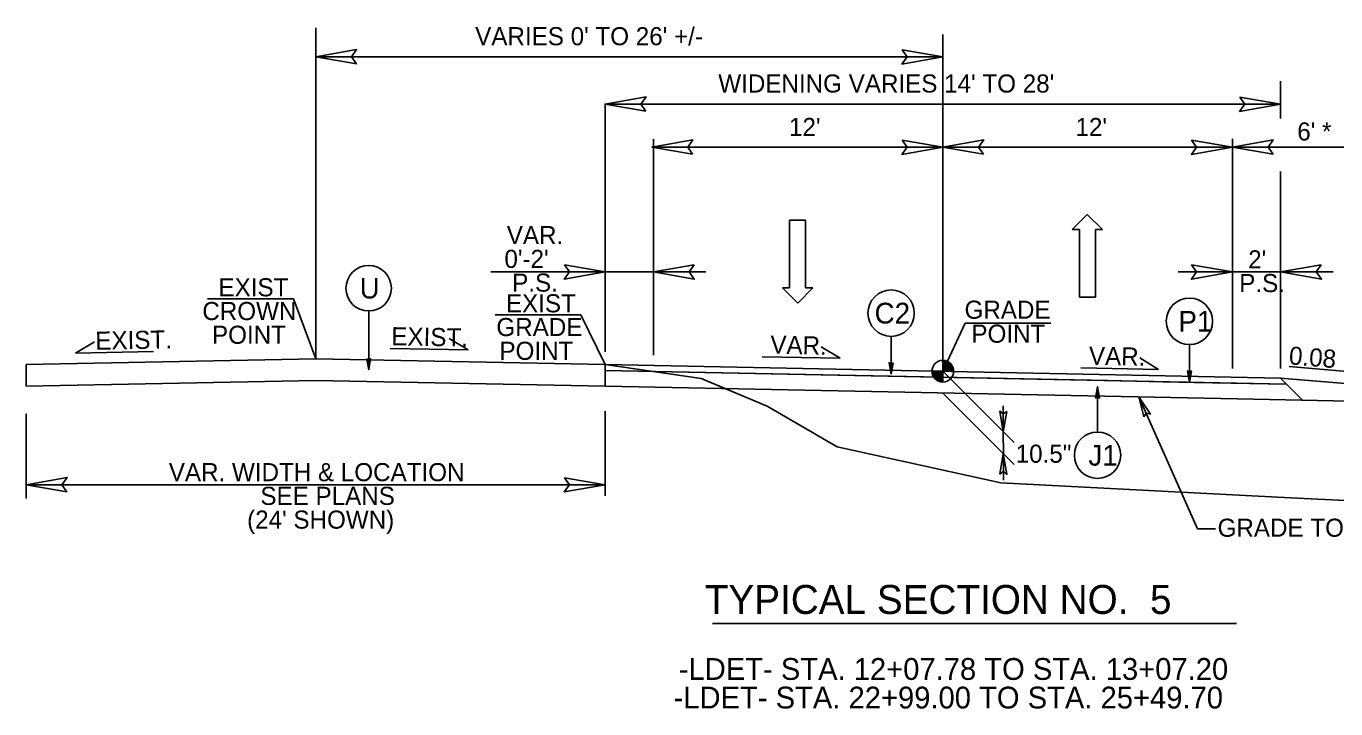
# Model space of a CAD drawing. Extents: x 1548135 to 1549339, y 868664 to 869085.
# Drawn here: x 1548331.5 to 1548385.7, y 868808.6 to 868836.9 of the extents above; entities that cross this region are included whole.
import ezdxf

# ---------------------------------------------------------------- set-up
doc = ezdxf.new("R2010")
doc.units = 0
for name, color, linetype in [('P_RDY_TC_Pvmt_Asphalt_Base_Course', 7, 'Continuous'), ('Prop Terminator CELL', 7, 'Continuous'), ('Sheet_Plan', 7, 'Continuous'), ('Typical Curb CELL', 7, 'Continuous'), ('Typical Grade Point Symbol CELL', 7, 'Continuous'), ('Typical Hinge Slope Arterial CELL', 7, 'Continuous'), ('Typical Hinge Slope Interstate CELL', 7, 'Continuous'), ('Typical Pavement Slope Information CELL', 7, 'Continuous'), ('Typical Shoulder Slope CELL', 7, 'Continuous'), ('Typical Shoulder Slope Information CELL', 7, 'Continuous'), ('Typical Terminator CELL', 7, 'Continuous'), ('Typical Text Centerline CELL', 7, 'Continuous'), ('Typical Text General CELL', 7, 'Continuous'), ('Typical Text Grade Point CELL', 7, 'Continuous'), ('Typical Text ID Circle CELL', 7, 'Continuous'), ('z - Construction', 7, 'Continuous')]:
    doc.layers.add(name, color=color, linetype=linetype)

msp = doc.modelspace()

# ---------------------------------------------------------------- linework, layer by layer
at = {"layer": 'P_RDY_TC_Pvmt_Asphalt_Base_Course'}
for points in [[(1548345.142, 868835.342), (1548343.455, 868835.633), (1548345.152, 868835.933), (1548344.936, 868835.633)], [(1548367.767, 868835.923), (1548369.455, 868835.633), (1548367.758, 868835.333), (1548367.974, 868835.633)], [(1548357.142, 868833.383), (1548355.455, 868833.674), (1548357.152, 868833.974), (1548356.936, 868833.674)], [(1548381.767, 868833.965), (1548383.455, 868833.674), (1548381.758, 868833.374), (1548381.974, 868833.674)], [(1548359.083, 868831.601), (1548357.395, 868831.891), (1548359.092, 868832.191), (1548358.877, 868831.891)], [(1548367.767, 868832.182), (1548369.455, 868831.891), (1548367.758, 868831.591), (1548367.974, 868831.891)], [(1548371.142, 868831.601), (1548369.455, 868831.891), (1548371.152, 868832.191), (1548370.936, 868831.891)], [(1548379.767, 868832.182), (1548381.455, 868831.891), (1548379.758, 868831.591), (1548379.974, 868831.891)], [(1548383.142, 868831.601), (1548381.455, 868831.891), (1548383.152, 868832.191), (1548382.936, 868831.891)], [(1548353.767, 868827.009), (1548355.455, 868826.718), (1548353.758, 868826.418), (1548353.974, 868826.718)], [(1548359.142, 868827.009), (1548357.455, 868826.718), (1548359.152, 868826.418), (1548358.936, 868826.718)], [(1548379.767, 868827.009), (1548381.455, 868826.718), (1548379.758, 868826.418), (1548379.974, 868826.718)], [(1548385.142, 868827.009), (1548383.455, 868826.718), (1548385.152, 868826.418), (1548384.936, 868826.718)], [(1548333.142, 868817.613), (1548331.455, 868817.904), (1548333.151, 868818.204), (1548332.936, 868817.904)], [(1548353.767, 868818.194), (1548355.455, 868817.904), (1548353.758, 868817.604), (1548353.974, 868817.904)]]:
    msp.add_lwpolyline(points, close=True, dxfattribs=at)
at = {"layer": 'Prop Terminator CELL'}
msp.add_lwpolyline([(1548355.455, 868822.885), (1548383.455, 868822.325), (1548383.705, 868822.07), (1548379.88, 868822.146), (1548378.58, 868822.172), (1548376.296, 868822.218), (1548355.455, 868822.635), (1548355.455, 868822.635)], close=True, dxfattribs=at)
at = {"layer": 'Sheet_Plan'}
msp.add_line((1548387.466, 868821.991), (1548383.455, 868822.325), dxfattribs=at)
at = {"layer": 'Typical Curb CELL'}
for p, q in [((1548369.455, 868822.605), (1548369.455, 868823.053)), ((1548369.007, 868822.605), (1548369.455, 868822.605)), ((1548369.454, 868822.157), (1548369.455, 868822.605)), ((1548369.455, 868822.605), (1548369.454, 868822.157)), ((1548369.902, 868822.605), (1548369.455, 868822.605))]:
    msp.add_line(p, q, dxfattribs=at)
for points in [[(1548369.459, 868823.053), (1548369.459, 868823.053), (1548369.459, 868822.605)], [(1548369.468, 868823.053), (1548369.468, 868822.605)], [(1548369.477, 868823.052), (1548369.477, 868822.605)], [(1548369.486, 868823.052), (1548369.486, 868822.605)], [(1548369.495, 868823.051), (1548369.495, 868822.605)], [(1548369.503, 868823.05), (1548369.503, 868822.605)], [(1548369.512, 868823.049), (1548369.512, 868822.605)], [(1548369.521, 868823.048), (1548369.521, 868822.605)], [(1548369.53, 868823.047), (1548369.53, 868822.605)], [(1548369.539, 868823.045), (1548369.539, 868822.605)], [(1548369.548, 868823.043), (1548369.548, 868822.605)], [(1548369.557, 868823.041), (1548369.557, 868822.605)], [(1548369.566, 868823.039), (1548369.566, 868822.605)], [(1548369.575, 868823.036), (1548369.575, 868822.605)], [(1548369.584, 868823.034), (1548369.584, 868822.605)], [(1548369.593, 868823.031), (1548369.593, 868822.605)], [(1548369.602, 868823.028), (1548369.602, 868822.605)], [(1548369.611, 868823.025), (1548369.611, 868822.605)], [(1548369.62, 868823.021), (1548369.62, 868822.605)], [(1548369.629, 868823.017), (1548369.629, 868822.605)], [(1548369.638, 868823.013), (1548369.638, 868822.605)], [(1548369.647, 868823.009), (1548369.647, 868822.605)], [(1548369.656, 868823.005), (1548369.656, 868822.605)], [(1548369.665, 868823), (1548369.665, 868822.605)], [(1548369.674, 868822.995), (1548369.674, 868822.605)], [(1548369.683, 868822.99), (1548369.683, 868822.605)], [(1548369.691, 868822.985), (1548369.691, 868822.605)], [(1548369.7, 868822.979), (1548369.7, 868822.605)], [(1548369.709, 868822.973), (1548369.709, 868822.605)], [(1548369.718, 868822.966), (1548369.718, 868822.605)], [(1548369.727, 868822.96), (1548369.727, 868822.605)], [(1548369.736, 868822.953), (1548369.736, 868822.605)], [(1548369.745, 868822.945), (1548369.745, 868822.605)], [(1548369.754, 868822.937), (1548369.754, 868822.605)], [(1548369.763, 868822.929), (1548369.763, 868822.605)], [(1548369.772, 868822.92), (1548369.772, 868822.605)], [(1548369.781, 868822.911), (1548369.781, 868822.605)], [(1548369.79, 868822.901), (1548369.79, 868822.605)], [(1548369.799, 868822.89), (1548369.799, 868822.605)], [(1548369.808, 868822.879), (1548369.808, 868822.605)], [(1548369.817, 868822.868), (1548369.817, 868822.605)], [(1548369.826, 868822.855), (1548369.826, 868822.605)], [(1548369.835, 868822.841), (1548369.835, 868822.605)], [(1548369.009, 868822.605), (1548369.009, 868822.556)], [(1548369.018, 868822.605), (1548369.018, 868822.503)], [(1548369.027, 868822.605), (1548369.027, 868822.472)], [(1548369.036, 868822.605), (1548369.036, 868822.445)], [(1548369.045, 868822.605), (1548369.045, 868822.424)], [(1548369.054, 868822.605), (1548369.054, 868822.405)], [(1548369.063, 868822.605), (1548369.063, 868822.388)], [(1548369.072, 868822.605), (1548369.072, 868822.372)], [(1548369.081, 868822.605), (1548369.081, 868822.358)], [(1548369.09, 868822.605), (1548369.09, 868822.345)], [(1548369.099, 868822.605), (1548369.099, 868822.333)], [(1548369.108, 868822.605), (1548369.108, 868822.322)], [(1548369.117, 868822.605), (1548369.117, 868822.312)], [(1548369.126, 868822.605), (1548369.126, 868822.302)], [(1548369.134, 868822.605), (1548369.134, 868822.292)], [(1548369.143, 868822.605), (1548369.143, 868822.283)], [(1548369.152, 868822.605), (1548369.152, 868822.275)], [(1548369.161, 868822.605), (1548369.161, 868822.267)], [(1548369.17, 868822.605), (1548369.17, 868822.259)], [(1548369.179, 868822.605), (1548369.179, 868822.252)], [(1548369.188, 868822.605), (1548369.188, 868822.245)], [(1548369.197, 868822.605), (1548369.197, 868822.239)], [(1548369.206, 868822.605), (1548369.206, 868822.233)], [(1548369.215, 868822.605), (1548369.215, 868822.227)], [(1548369.224, 868822.605), (1548369.224, 868822.221)], [(1548369.233, 868822.605), (1548369.233, 868822.216)], [(1548369.242, 868822.605), (1548369.242, 868822.211)], [(1548369.251, 868822.605), (1548369.251, 868822.206)], [(1548369.26, 868822.605), (1548369.26, 868822.202)], [(1548369.269, 868822.605), (1548369.269, 868822.198)], [(1548369.278, 868822.605), (1548369.278, 868822.194)], [(1548369.287, 868822.605), (1548369.287, 868822.19)], [(1548369.296, 868822.605), (1548369.296, 868822.186)], [(1548369.305, 868822.605), (1548369.305, 868822.183)], [(1548369.313, 868822.605), (1548369.313, 868822.18)], [(1548369.322, 868822.605), (1548369.322, 868822.177)], [(1548369.331, 868822.605), (1548369.331, 868822.175)], [(1548369.34, 868822.605), (1548369.34, 868822.172)], [(1548369.349, 868822.605), (1548369.349, 868822.17)], [(1548369.358, 868822.605), (1548369.358, 868822.168)], [(1548369.367, 868822.605), (1548369.367, 868822.166)], [(1548369.376, 868822.605), (1548369.376, 868822.164)], [(1548369.385, 868822.605), (1548369.385, 868822.163)], [(1548369.394, 868822.605), (1548369.394, 868822.161)], [(1548369.403, 868822.605), (1548369.403, 868822.16)], [(1548369.412, 868822.605), (1548369.412, 868822.159)], [(1548369.421, 868822.605), (1548369.421, 868822.158)], [(1548369.43, 868822.605), (1548369.43, 868822.158)], [(1548369.439, 868822.605), (1548369.439, 868822.157)], [(1548369.448, 868822.605), (1548369.448, 868822.157), (1548369.448, 868822.157)], [(1548369.844, 868822.826), (1548369.844, 868822.605)], [(1548369.853, 868822.81), (1548369.853, 868822.605)], [(1548369.862, 868822.791), (1548369.862, 868822.605)], [(1548369.87, 868822.77), (1548369.87, 868822.605)], [(1548369.879, 868822.745), (1548369.879, 868822.605)], [(1548369.888, 868822.714), (1548369.888, 868822.605)], [(1548369.897, 868822.669), (1548369.897, 868822.605)]]:
    msp.add_lwpolyline(points, dxfattribs=at)
msp.add_circle((1548369.454, 868822.605), 0.448, dxfattribs=at)
for start, end in [(359.9905, 89.9905), (179.9905, 269.9905)]:
    msp.add_arc((1548369.454, 868822.605), 0.448, start, end, dxfattribs=at)
at = {"layer": 'Typical Grade Point Symbol CELL'}
for p, q in [((1548343.455, 868823.165), (1548343.455, 868836.836)), ((1548369.455, 868822.605), (1548369.455, 868836.556)), ((1548355.455, 868835.633), (1548343.455, 868835.633)), ((1548355.455, 868835.633), (1548369.455, 868835.633)), ((1548383.455, 868833.081), (1548383.455, 868834.627)), ((1548369.455, 868833.674), (1548355.455, 868833.674)), ((1548369.455, 868833.674), (1548383.455, 868833.674)), ((1548357.455, 868823.272), (1548357.455, 868832.217)), ((1548381.455, 868822.725), (1548381.455, 868832.237)), ((1548381.455, 868822.725), (1548381.455, 868832.237)), ((1548369.455, 868831.891), (1548357.455, 868831.891)), ((1548369.455, 868831.891), (1548387.466, 868831.891)), ((1548383.455, 868822.725), (1548383.455, 868830.875)), ((1548350.711, 868826.718), (1548359.635, 868826.718)), ((1548379.205, 868826.718), (1548385.635, 868826.718))]:
    msp.add_line(p, q, dxfattribs=at)
at = {"layer": 'Typical Hinge Slope Arterial CELL'}
for p, q in [((1548342.531, 868825.611), (1548338.974, 868825.611)), ((1548354.447, 868824.947), (1548350.89, 868824.947)), ((1548370.378, 868824.591), (1548373.935, 868824.591))]:
    msp.add_line(p, q, dxfattribs=at)
at = {"layer": 'Typical Hinge Slope Interstate CELL'}
for p, q in [((1548345.652, 868825.102), (1548345.652, 868822.666)), ((1548367.31, 868824.051), (1548367.31, 868822.489)), ((1548379.675, 868823.713), (1548379.675, 868822.15)), ((1548343.455, 868823.125), (1548331.455, 868822.885)), ((1548331.455, 868821.985), (1548331.455, 868822.885)), ((1548343.455, 868823.125), (1548355.455, 868822.885)), ((1548355.455, 868822.885), (1548355.455, 868821.985)), ((1548383.705, 868822.07), (1548355.455, 868822.635)), ((1548372.406, 868819.653), (1548369.455, 868822.605)), ((1548343.455, 868822.225), (1548331.455, 868821.985)), ((1548343.455, 868822.225), (1548355.455, 868821.985)), ((1548381.675, 868821.46), (1548355.455, 868821.985)), ((1548375.867, 868820.086), (1548375.867, 868821.964)), ((1548372.405, 868818.743), (1548369.453, 868821.695)), ((1548371.96, 868821.178), (1548371.962, 868818.088))]:
    msp.add_line(p, q, dxfattribs=at)
for points in [[(1548345.573, 868823.125), (1548345.652, 868822.666), (1548345.734, 868823.128), (1548345.652, 868823.069)], [(1548367.391, 868822.957), (1548367.31, 868822.489), (1548367.227, 868822.96), (1548367.31, 868822.9)], [(1548379.756, 868822.619), (1548379.675, 868822.15), (1548379.592, 868822.622), (1548379.675, 868822.562)], [(1548375.786, 868821.496), (1548375.867, 868821.964), (1548375.95, 868821.493), (1548375.867, 868821.553)], [(1548377.789, 868820.712), (1548377.58, 868821.542), (1548378.061, 868820.828), (1548377.88, 868820.865)], [(1548372.105, 868820.944), (1548371.96, 868820.1), (1548371.81, 868820.948), (1548371.96, 868820.841)], [(1548371.814, 868818.345), (1548371.96, 868819.189), (1548372.11, 868818.34), (1548371.96, 868818.448)]]:
    msp.add_lwpolyline(points, close=True, dxfattribs=at)
for points in [[(1548355.455, 868822.885), (1548359.435, 868822.302), (1548362.167, 868821.156), (1548365.071, 868819.475), (1548371.864, 868817.984), (1548383.869, 868817.359), (1548398.104, 868816.672)], [(1548377.58, 868821.542), (1548380.004, 868816.077), (1548380.755, 868816.077)]]:
    msp.add_lwpolyline(points, dxfattribs=at)
for centre, radius in [((1548345.652, 868826.044), 0.942), ((1548367.31, 868825.013), 0.962), ((1548379.675, 868824.674), 0.962), ((1548375.867, 868819.125), 0.962)]:
    msp.add_circle(centre, radius, dxfattribs=at)
at = {"layer": 'Typical Pavement Slope Information CELL'}
for p, q in [((1548349.777, 868823.487), (1548348.994, 868823.961)), ((1548333.504, 868823.357), (1548334.287, 868823.83)), ((1548333.504, 868823.357), (1548336.733, 868823.422)), ((1548349.777, 868823.487), (1548346.547, 868823.552)), ((1548365.191, 868823.144), (1548364.408, 868823.618)), ((1548365.191, 868823.144), (1548361.962, 868823.209)), ((1548378.398, 868822.683), (1548377.615, 868823.156)), ((1548378.398, 868822.683), (1548375.168, 868822.748)), ((1548386.688, 868822.556), (1548383.805, 868822.797))]:
    msp.add_line(p, q, dxfattribs=at)
at = {"layer": 'Typical Shoulder Slope CELL'}
for p, q in [((1548342.531, 868825.611), (1548343.455, 868823.125)), ((1548354.447, 868824.947), (1548355.455, 868822.885)), ((1548370.378, 868824.591), (1548369.455, 868822.605))]:
    msp.add_line(p, q, dxfattribs=at)
at = {"layer": 'Typical Shoulder Slope Information CELL'}
for p, q in [((1548363.101, 868826.061), (1548363.101, 868828.861)), ((1548363.101, 868828.861), (1548363.761, 868828.861)), ((1548363.761, 868828.861), (1548363.761, 868826.061)), ((1548374.819, 868828.475), (1548375.439, 868829.105)), ((1548375.439, 868829.105), (1548376.079, 868828.475)), ((1548375.119, 868828.475), (1548374.819, 868828.475)), ((1548375.119, 868825.675), (1548375.119, 868828.475)), ((1548376.079, 868828.475), (1548375.779, 868828.475)), ((1548375.779, 868828.475), (1548375.779, 868825.675)), ((1548363.441, 868825.431), (1548362.801, 868826.061)), ((1548362.801, 868826.061), (1548363.101, 868826.061)), ((1548364.061, 868826.061), (1548363.441, 868825.431)), ((1548363.761, 868826.061), (1548364.061, 868826.061)), ((1548375.779, 868825.675), (1548375.119, 868825.675))]:
    msp.add_line(p, q, dxfattribs=at)
at = {"layer": 'Typical Terminator CELL'}
for p, q in [((1548331.455, 868817.333), (1548331.455, 868820.836)), ((1548355.455, 868817.449), (1548355.455, 868820.952)), ((1548331.455, 868817.904), (1548355.455, 868817.904)), ((1548359.903, 868812.148), (1548381.624, 868812.148))]:
    msp.add_line(p, q, dxfattribs=at)
at = {"layer": 'Typical Text Grade Point CELL'}
for p, q in [((1548355.455, 868822.885), (1548383.455, 868822.325)), ((1548383.455, 868822.325), (1548384.357, 868821.406)), ((1548381.675, 868821.46), (1548388.814, 868821.317))]:
    msp.add_line(p, q, dxfattribs=at)
at = {"layer": 'Typical Text ID Circle CELL'}
msp.add_line((1548355.455, 868833.674), (1548355.455, 868823.413), dxfattribs=at)

# ---------------------------------------------------------------- texts
at = {"layer": 'Typical Hinge Slope Arterial CELL'}
msp.add_text('TYPICAL SECTION NO.  5', height=1.2, dxfattribs=at).set_placement((1548359.584, 868812.55))
at = {"layer": 'Typical Hinge Slope Interstate CELL'}
for s, height, p in [('U', 0.844, (1548345.285, 868825.622)), ('C2', 0.8608, (1548366.624, 868824.582)), ('P1', 0.8608, (1548379.219, 868824.244)), ('10.5"', 0.75, (1548372.474, 868818.814)), ('J1', 0.8608, (1548375.488, 868818.694)), ('GRADE TO THIS LINE', 0.75, (1548380.843, 868815.747))]:
    msp.add_text(s, height=height, dxfattribs=at).set_placement(p)
at = {"layer": 'Typical Pavement Slope Information CELL'}
for s, rotation, p in [('EXIST.', 1.1456, (1548334.327, 868823.493)), ('EXIST.', 358.8544, (1548346.585, 868823.686)), ('VAR.', 358.8544, (1548362.297, 868823.337)), ('VAR.', 358.8544, (1548375.503, 868822.876))]:
    msp.add_text(s, height=0.75, rotation=rotation, dxfattribs=at).set_placement(p)
at = {"layer": 'Typical Shoulder Slope CELL'}
for s, p in [("VARIES 0' TO 26' +/-", (1548350.068, 868836.112)), ("WIDENING VARIES 14' TO 28'", (1548360.146, 868834.153)), ("12'", (1548363.077, 868832.352)), ("12'", (1548374.954, 868832.352)), ("6' *", (1548384.147, 868832.166)), ('EXIST', (1548339.426, 868825.709)), ('EXIST', (1548351.342, 868825.045)), ('CROWN', (1548338.757, 868824.725)), ('GRADE', (1548370.353, 868824.781)), ('POINT', (1548339.157, 868823.742)), ('GRADE', (1548350.946, 868824.062)), ('POINT', (1548370.638, 868823.787)), ('POINT', (1548351.072, 868823.078)), ('VAR. WIDTH & LOCATION', (1548337.366, 868818.05)), ('SEE PLANS', (1548341.163, 868817.067)), ("(24' SHOWN)", (1548340.613, 868816.084))]:
    msp.add_text(s, height=0.75, dxfattribs=at).set_placement(p)
at = {"layer": 'Typical Text Centerline CELL'}
for s, p in [('VAR. ', (1548351.377, 868827.871)), ("0'-2'", (1548351.28, 868826.887)), ("2'", (1548382.11, 868826.867)), ('P.S.', (1548351.601, 868825.904)), ('P.S.', (1548381.741, 868825.884))]:
    msp.add_text(s, height=0.75, dxfattribs=at).set_placement(p)
at = {"layer": 'Typical Text General CELL'}
for s, p in [('-LDET- STA. 12+07.78 TO STA. 13+07.20', (1548358.508, 868809.818)), ('-LDET- STA. 22+99.00 TO STA. 25+49.70', (1548358.292, 868808.633))]:
    msp.add_text(s, height=0.90387, dxfattribs=at).set_placement(p)
at = {"layer": 'z - Construction'}
msp.add_text('0.08', height=0.75, rotation=355.2385, dxfattribs=at).set_placement((1548383.78, 868822.894))

doc.saveas('drawing.dxf')
